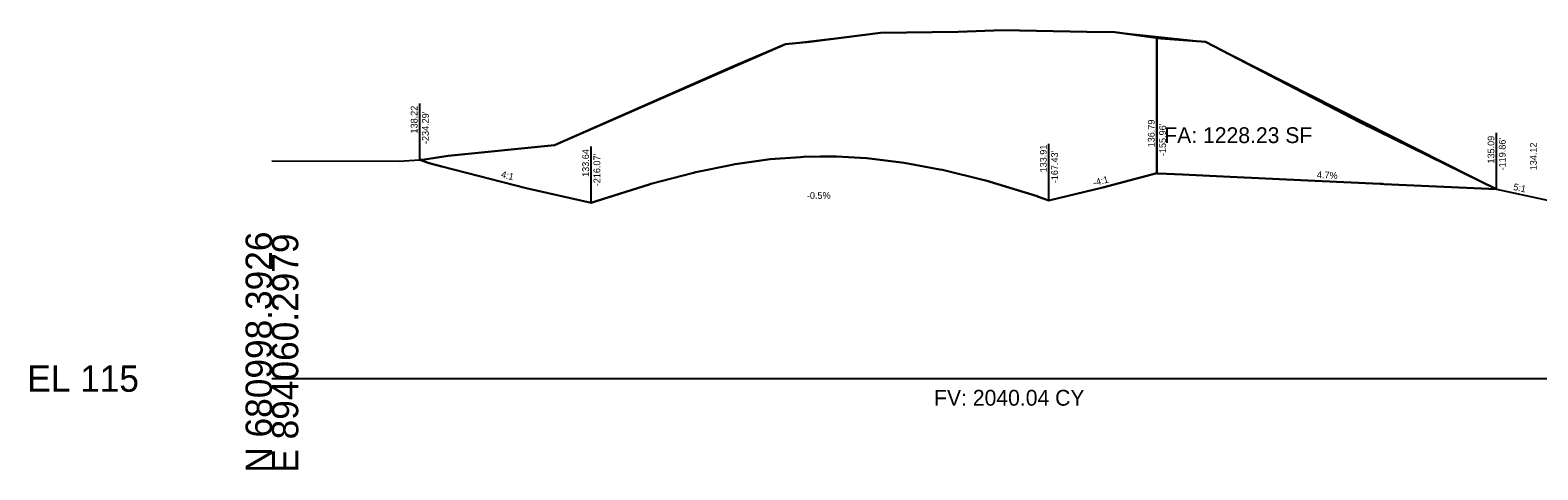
# Model space of a CAD drawing. Extents: x -26 to 4403, y -13 to 9578.
# Drawn here: x 974.3 to 1134.5, y 9490.3 to 9537 of the extents above; entities that cross this region are included whole.
import ezdxf

# ---------------------------------------------------------------- set-up
doc = ezdxf.new("R2010")
doc.units = 0
for name, color, linetype in [('1', 7, 'Continuous'), ('Draft_XS_Grid', 7, 'Continuous'), ('DRAINAGE_SPUR_DIKES', 7, 'Continuous'), ('DTM_CORRIDOR', 7, 'Continuous'), ('DTM_X_GROUND', 7, 'Continuous'), ('SLOPE_STAKES_FILL', 7, 'Continuous'), ('XS_CELL', 7, 'Continuous'), ('XS_M_SHAPES_EARTHWORK', 7, 'Continuous'), ('XS_P_GROUND', 7, 'Continuous'), ('XS_P_TX_CLEARZONE', 7, 'Continuous'), ('XS_P_TX_FS_BS', 7, 'Continuous'), ('XS_SHEET_EW_TX_AREA', 7, 'Continuous'), ('XS_SHEET_EW_TX_VOLUME', 7, 'Continuous')]:
    doc.layers.add(name, color=color, linetype=linetype)

msp = doc.modelspace()

# ---------------------------------------------------------------- linework, layer by layer
at = {"layer": '1'}
for p, q in [((1054.56, 9535.49), (1064.65, 9536.71)), ((1089.58, 9536.77), (1099.21, 9535.76)), ((1030.01, 9524.78), (1054.56, 9535.49)), ((1099.21, 9535.76), (1130.14, 9520.09))]:
    msp.add_line(p, q, dxfattribs=at)
at = {"layer": 'DTM_X_GROUND'}
msp.add_lwpolyline([(1000, 9523.1), (1013.53, 9523.08), (1016.21, 9523.25), (1018.72, 9523.64), (1030.01, 9524.78), (1049.23, 9533.23), (1054.56, 9535.49), (1057.15, 9535.76), (1064.65, 9536.71), (1072.91, 9536.82), (1077.67, 9536.99), (1086.6, 9536.82), (1089.58, 9536.77), (1094.46, 9536.11), (1099.21, 9535.76), (1115.61, 9527.22), (1130.14, 9520.09), (1150.64, 9515.7)], dxfattribs=at)
at = {"layer": 'XS_CELL'}
msp.add_line((1000, 9500), (1250, 9500), dxfattribs=at)
at = {"layer": 'XS_M_SHAPES_EARTHWORK'}
for points in [[(1015.71, 9523.22), (1016.21, 9523.25), (1018.72, 9523.64), (1030.01, 9524.78), (1049.23, 9533.23), (1054.56, 9535.49), (1057.15, 9535.76), (1064.65, 9536.71), (1072.91, 9536.82), (1077.67, 9536.99), (1086.6, 9536.82), (1089.58, 9536.77), (1094.04, 9536.16), (1094.04, 9521.79), (1088.31, 9520.27), (1082.57, 9518.91), (1081.35, 9519.34), (1081.31, 9519.35), (1075.85, 9521.01), (1075.67, 9521.05), (1071.25, 9522.15), (1070.98, 9522.2), (1067.2, 9522.91), (1066.9, 9522.95), (1063.5, 9523.37), (1063.17, 9523.39), (1059.98, 9523.58), (1059.83, 9523.58), (1058.44, 9523.59), (1058.25, 9523.59), (1056.5, 9523.55), (1056.17, 9523.52), (1052.95, 9523.28), (1049.48, 9522.8), (1049.18, 9522.76), (1048.89, 9522.7), (1045.03, 9521.92), (1044.78, 9521.85), (1040.25, 9520.67), (1040.08, 9520.61), (1034.46, 9518.84), (1034.44, 9518.83), (1033.93, 9518.64), (1027.02, 9520.22), (1018.05, 9522.53), (1016.69, 9522.88)], [(1094.04, 9521.78), (1094.04, 9536.16), (1094.46, 9536.11), (1099.21, 9535.76), (1115.61, 9527.22), (1130.14, 9520.09), (1118.17, 9520.65), (1118.01, 9520.66), (1117.78, 9520.67), (1110.82, 9521), (1101.08, 9521.45), (1096.75, 9521.65), (1095.05, 9521.73), (1094.06, 9521.78)]]:
    msp.add_lwpolyline(points, close=True, dxfattribs=at)
at = {"layer": 'XS_P_GROUND'}
for points in [[(1130.14, 9520.09), (1115.61, 9527.22), (1099.21, 9535.76), (1094.46, 9536.11), (1089.58, 9536.77), (1086.6, 9536.82), (1077.67, 9536.99), (1072.91, 9536.82), (1064.65, 9536.71), (1057.15, 9535.76), (1054.56, 9535.49), (1049.23, 9533.23), (1030.01, 9524.78), (1018.72, 9523.64), (1016.21, 9523.25), (1015.71, 9523.22)], [(1015.71, 9523.22), (1016.69, 9522.88), (1018.05, 9522.53), (1027.02, 9520.22), (1033.93, 9518.64)], [(1015.71, 9523.22), (1016.69, 9522.88), (1018.05, 9522.53), (1027.02, 9520.22), (1033.93, 9518.64)], [(1033.93, 9518.64), (1034.44, 9518.83), (1034.46, 9518.84), (1040.08, 9520.61), (1040.25, 9520.67), (1044.78, 9521.85), (1045.03, 9521.92), (1048.89, 9522.7), (1049.18, 9522.76), (1049.48, 9522.8), (1052.95, 9523.28), (1056.17, 9523.52), (1056.5, 9523.55), (1058.25, 9523.59), (1058.44, 9523.59)], [(1033.93, 9518.64), (1034.44, 9518.83), (1034.46, 9518.84), (1040.08, 9520.61), (1040.25, 9520.67), (1044.78, 9521.85), (1045.03, 9521.92), (1048.89, 9522.7), (1049.18, 9522.76), (1049.48, 9522.8), (1052.95, 9523.28), (1056.17, 9523.52), (1056.5, 9523.55), (1058.25, 9523.59), (1058.44, 9523.59)], [(1058.44, 9523.59), (1059.83, 9523.58), (1059.98, 9523.58), (1063.17, 9523.39), (1063.5, 9523.37), (1066.9, 9522.95), (1067.2, 9522.91), (1070.98, 9522.2), (1071.25, 9522.15), (1075.67, 9521.05), (1075.85, 9521.01), (1081.31, 9519.35), (1081.35, 9519.34), (1082.57, 9518.91)], [(1058.44, 9523.59), (1059.83, 9523.58), (1059.98, 9523.58), (1063.17, 9523.39), (1063.5, 9523.37), (1066.9, 9522.95), (1067.2, 9522.91), (1070.98, 9522.2), (1071.25, 9522.15), (1075.67, 9521.05), (1075.85, 9521.01), (1081.31, 9519.35), (1081.35, 9519.34), (1082.57, 9518.91)], [(1082.57, 9518.91), (1088.31, 9520.27), (1094.04, 9521.79)], [(1082.57, 9518.91), (1088.31, 9520.27), (1094.04, 9521.79)], [(1094.04, 9521.79), (1094.06, 9521.78), (1095.05, 9521.73), (1096.75, 9521.65), (1101.08, 9521.45), (1110.82, 9521), (1117.78, 9520.67), (1118.01, 9520.66), (1118.17, 9520.65), (1130.14, 9520.09)], [(1094.04, 9521.78), (1094.06, 9521.78), (1095.05, 9521.73), (1096.75, 9521.65), (1101.08, 9521.45), (1110.82, 9521), (1117.78, 9520.67), (1118.01, 9520.66), (1118.17, 9520.65), (1130.14, 9520.09), (1130.14, 9520.09)]]:
    msp.add_lwpolyline(points, dxfattribs=at)
at = {"layer": 'XS_P_TX_CLEARZONE'}
for p, q in [((1015.71, 9523.22), (1015.71, 9529.22)), ((1015.71, 9523.22), (1015.71, 9529.22)), ((1015.71, 9523.22), (1015.71, 9529.22)), ((1094.04, 9521.79), (1094.04, 9527.79)), ((1094.04, 9521.79), (1094.04, 9527.79)), ((1094.04, 9521.79), (1094.04, 9527.79)), ((1033.93, 9518.64), (1033.93, 9524.64)), ((1033.93, 9518.64), (1033.93, 9524.64)), ((1033.93, 9518.64), (1033.93, 9524.64)), ((1082.57, 9518.91), (1082.57, 9524.91)), ((1082.57, 9518.91), (1082.57, 9524.91)), ((1082.57, 9518.91), (1082.57, 9524.91)), ((1082.57, 9518.91), (1082.57, 9524.91)), ((1082.57, 9518.91), (1082.57, 9524.91)), ((1082.57, 9518.91), (1082.57, 9524.91)), ((1130.14, 9520.09), (1130.14, 9526.09)), ((1130.14, 9520.09), (1130.14, 9526.09)), ((1130.14, 9520.09), (1130.14, 9526.09)), ((1130.14, 9520.09), (1130.14, 9526.09)), ((1130.14, 9520.09), (1130.14, 9526.09)), ((1130.14, 9520.09), (1130.14, 9526.09)), ((1130.14, 9520.09), (1130.14, 9526.09)), ((1130.14, 9520.09), (1130.14, 9526.09)), ((1130.14, 9520.09), (1130.14, 9526.09))]:
    msp.add_line(p, q, dxfattribs=at)

# ---------------------------------------------------------------- texts
at = {"layer": 'Draft_XS_Grid'}
msp.add_text('-', height=0.0001, dxfattribs=at).set_placement((1000, 9500))
at = {"layer": 'DRAINAGE_SPUR_DIKES'}
for p in [(1015.67, 9523.16), (1094, 9521.73)]:
    msp.add_text('X', height=0.12, dxfattribs=at).set_placement(p)
at = {"layer": 'DTM_CORRIDOR'}
for p in [(1130.1, 9520.03), (1033.89, 9518.58), (1082.53, 9518.85)]:
    msp.add_text('X', height=0.12, dxfattribs=at).set_placement(p)
at = {"layer": 'SLOPE_STAKES_FILL'}
msp.add_text('X', height=0.12, dxfattribs=at).set_placement((1130.1, 9520.03))
at = {"layer": 'XS_CELL'}
for s, p in [('N 680998.3926', (1000, 9490)), ('E 894060.2979', (1002.8, 9490))]:
    msp.add_text(s, height=2.8, rotation=90, dxfattribs=at).set_placement(p)
msp.add_text('EL 115', height=2.8, dxfattribs=at).set_placement((974, 9498.6))
at = {"layer": 'XS_P_TX_CLEARZONE'}
for s, p in [('138.22', (1015.47, 9526.02)), ('138.22', (1015.47, 9526.02)), ('138.22', (1015.47, 9526.02)), ("-234.29'", (1016.67, 9524.9)), ("-234.29'", (1016.67, 9524.9)), ("-234.29'", (1016.67, 9524.9)), ('136.79', (1093.8, 9524.55)), ('136.79', (1093.8, 9524.55)), ('136.79', (1093.8, 9524.55)), ("-155.96'", (1095, 9523.62)), ("-155.96'", (1095, 9523.62)), ("-155.96'", (1095, 9523.62)), ('133.91', (1082.33, 9521.89)), ('133.91', (1082.33, 9521.89)), ('133.91', (1082.33, 9521.89)), ('133.91', (1082.33, 9521.89)), ('133.91', (1082.33, 9521.89)), ('133.91', (1082.33, 9521.89)), ('135.09', (1129.9, 9522.83)), ('135.09', (1129.9, 9522.83)), ('135.09', (1129.9, 9522.83)), ('135.09', (1129.9, 9522.83)), ('135.09', (1129.9, 9522.83)), ('135.09', (1129.9, 9522.83)), ('135.09', (1129.9, 9522.83)), ('135.09', (1129.9, 9522.83)), ('135.09', (1129.9, 9522.83)), ("-119.86'", (1131.1, 9522.1)), ("-119.86'", (1131.1, 9522.1)), ("-119.86'", (1131.1, 9522.1)), ("-119.86'", (1131.1, 9522.1)), ("-119.86'", (1131.1, 9522.1)), ("-119.86'", (1131.1, 9522.1)), ("-119.86'", (1131.1, 9522.1)), ("-119.86'", (1131.1, 9522.1)), ("-119.86'", (1131.1, 9522.1)), ('134.12', (1134.41, 9522.11)), ('134.12', (1134.41, 9522.11)), ('134.12', (1134.41, 9522.11)), ('134.12', (1134.41, 9522.11)), ('134.12', (1134.41, 9522.11)), ('134.12', (1134.41, 9522.11)), ('133.64', (1033.69, 9521.41)), ('133.64', (1033.69, 9521.41)), ('133.64', (1033.69, 9521.41)), ("-216.07'", (1034.89, 9520.42)), ("-216.07'", (1034.89, 9520.42)), ("-216.07'", (1034.89, 9520.42)), ("-167.43'", (1083.53, 9520.74)), ("-167.43'", (1083.53, 9520.74)), ("-167.43'", (1083.53, 9520.74)), ("-167.43'", (1083.53, 9520.74)), ("-167.43'", (1083.53, 9520.74)), ("-167.43'", (1083.53, 9520.74))]:
    msp.add_text(s, height=0.72, rotation=90, dxfattribs=at).set_placement(p)
at = {"layer": 'XS_P_TX_FS_BS'}
for s, rotation, p in [('4:1', 345.9009, (1024.3, 9521.37)), ('4:1', 345.9009, (1024.3, 9521.37)), ('4:1', 345.9009, (1024.3, 9521.37)), ('-4:1', 14.0951, (1087.35, 9520.42)), ('-4:1', 14.0951, (1087.35, 9520.42)), ('-4:1', 14.0951, (1087.35, 9520.42)), ('4.7%', 357.3082, (1111.03, 9521.29)), ('4.7%', 357.3082, (1111.03, 9521.29)), ('4.7%', 357.3082, (1111.03, 9521.29)), ('5:1', 347.9192, (1131.86, 9520.03)), ('5:1', 347.9192, (1131.86, 9520.03)), ('5:1', 347.9192, (1131.86, 9520.03)), ('-0.5%', 0.3121, (1056.85, 9519.07)), ('-0.5%', 0.3121, (1056.85, 9519.07)), ('-0.5%', 0.3121, (1056.85, 9519.07))]:
    msp.add_text(s, height=0.72, rotation=rotation, dxfattribs=at).set_placement(p)
at = {"layer": 'XS_SHEET_EW_TX_AREA'}
msp.add_text('FA: 1228.23 SF', height=1.68, dxfattribs=at).set_placement((1094.82, 9525))
at = {"layer": 'XS_SHEET_EW_TX_VOLUME'}
msp.add_text('FV: 2040.04 CY', height=1.68, dxfattribs=at).set_placement((1070.36, 9497.12))

doc.saveas('drawing.dxf')
